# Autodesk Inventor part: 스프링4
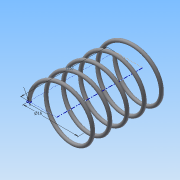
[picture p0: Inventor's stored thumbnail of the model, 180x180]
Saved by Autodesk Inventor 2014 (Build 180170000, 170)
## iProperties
Created: 2015-06
Part Number: 스프링4
Material: 강철, 연강
Document SubType Name: Modeling
Designer: Administrator
Density: 7.86 g/cm^3
Appearance: 강철
Mass: 1.53609 g
Surface Area: 7.89657 cm^2
Volume: 0.195431 cm^3
Author: Administrator
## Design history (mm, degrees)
sketch "스케치1"
  geometry: L1 (0, 0)-(-8, 0); L2 (-8, 0)-(-8, 21.5); L3 (-8, 21.5)-(0, 21.5); L4 (0, 21.5)-(0, 0); C1 r 0.5 at (-8, 0)
  constraints: 8 end point, 2 parallel, 1 centre point, 1 coincident, 1 horizontal, 1 perpendicular
  dimensions: "d0" = 1 diameter of C1; "d1" = 16 diameter of L2 L4; "d2" = 21.5 distance of L1.end L2.end (derived)
feature "코일1" sketch "스케치1" pitch "d3" = 10; turns "d5" = 5; dims "d4" = 21.5 (= d2), "d6" = 0, angle "d7" = 90 deg, angle "d8" = 90 deg, "d9" = 0, "d10" = 0
sketch "스케치2"
  geometry: L1 (8.5, 0)-(7.5, 0) reference; 1 further point
  constraints: 1 horizontal alignment
extrude "돌출1" cut sketch "스케치2" stored distance "d11" = 10; taper "d12" = 0 deg
node "작업 평면1"
sketch "스케치3"
  geometry: L1 (7.5, 0)-(8.5, 0) reference; 1 further point
  constraints: 1 horizontal alignment
extrude "돌출2" cut sketch "스케치3" stored distance "d14" = 10; taper "d15" = 0 deg
node "솔리드1"
node "절단 모서리 투영1"
node "절단 모서리 투영2"
other parameters: "d13" = 21.5 (= d2)
